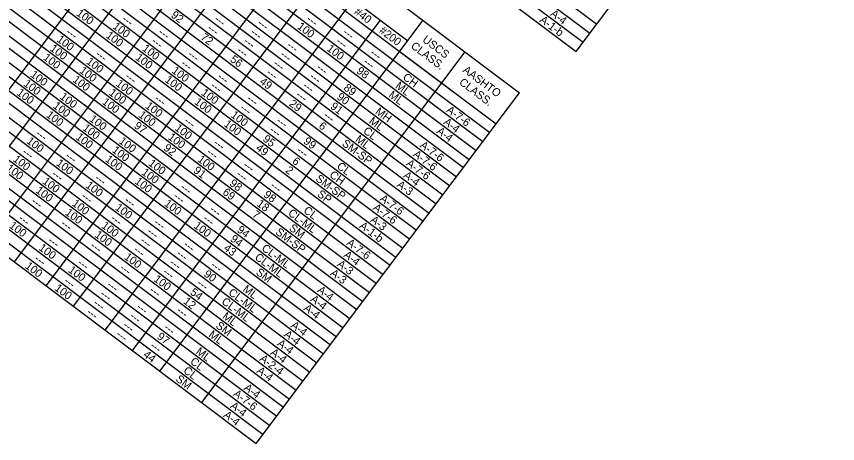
# Model space of a CAD drawing. Extents: x 627484.2 to 627514.4, y 367972.1 to 367996.9.
# Drawn here: x 627508.72 to 627514.36, y 367977.2 to 367980.14 of the extents above; entities that cross this region are included whole.
import ezdxf

# ---------------------------------------------------------------- set-up
doc = ezdxf.new("R2010")
doc.units = 0
doc.layers.add('Default', color=7, linetype='Continuous')

msp = doc.modelspace()

# ---------------------------------------------------------------- linework, layer by layer
at = {"layer": 'Default'}
for p, q in [((627508.2282, 367983.4455), (627512.7035, 367980.085)), ((627508.1814, 367983.3831), (627512.6566, 367980.0226)), ((627508.1346, 367983.3207), (627512.6098, 367979.9602)), ((627508.0877, 367983.2583), (627512.563, 367979.8978)), ((627507.6986, 367982.9746), (627512.1738, 367979.6141)), ((627507.5376, 367982.7602), (627512.0128, 367979.3997)), ((627507.4937, 367982.7017), (627511.9689, 367979.3412)), ((627507.4468, 367982.6393), (627511.9221, 367979.2788)), ((627507.4, 367982.5769), (627511.8753, 367979.2164)), ((627507.3532, 367982.5146), (627511.8284, 367979.1541)), ((627507.3122, 367982.46), (627511.7874, 367979.0995)), ((627507.2654, 367982.3976), (627511.7406, 367979.0371)), ((627507.2185, 367982.3352), (627511.6938, 367978.9747)), ((627507.1717, 367982.2729), (627511.6469, 367978.9124)), ((627512.563, 367979.8978), (627514.3574, 367982.2875)), ((627507.1248, 367982.2105), (627511.6001, 367978.85)), ((627507.078, 367982.1481), (627511.5533, 367978.7876)), ((627507.037, 367982.0936), (627511.5123, 367978.733)), ((627506.9902, 367982.0312), (627511.4654, 367978.6707)), ((627506.9434, 367981.9688), (627511.4186, 367978.6083)), ((627506.8965, 367981.9064), (627511.3718, 367978.5459)), ((627506.8497, 367981.8441), (627511.3249, 367978.4836)), ((627506.8087, 367981.7895), (627511.2839, 367978.429)), ((627506.7619, 367981.7271), (627511.2371, 367978.3666)), ((627506.715, 367981.6647), (627511.1903, 367978.3042)), ((627506.6682, 367981.6024), (627511.1434, 367978.2419)), ((627506.6214, 367981.54), (627511.0966, 367978.1795)), ((627506.5804, 367981.4854), (627511.0556, 367978.1249)), ((627506.5335, 367981.423), (627511.0088, 367978.0625)), ((627506.4867, 367981.3607), (627510.9619, 367978.0002)), ((627506.4399, 367981.2983), (627510.9151, 367977.9378)), ((627508.1116, 367978.8969), (627509.9206, 367981.306)), ((627506.3989, 367981.2437), (627510.8741, 367977.8832)), ((627506.352, 367981.1813), (627510.8273, 367977.8208)), ((627506.3052, 367981.119), (627510.7805, 367977.7585)), ((627509.8152, 367981.1657), (627511.4057, 367979.9714)), ((627506.2584, 367981.0566), (627510.7336, 367977.6961)), ((627508.2987, 367978.7564), (627510.0024, 367981.0252)), ((627506.2115, 367980.9942), (627510.6868, 367977.6337)), ((627506.1647, 367980.9319), (627510.6399, 367977.5714)), ((627506.1179, 367980.8695), (627510.5931, 367977.509)), ((627508.517, 367978.5924), (627510.2207, 367980.8613)), ((627506.0769, 367980.8149), (627510.5521, 367977.4544)), ((627506.03, 367980.7525), (627510.5053, 367977.392)), ((627508.7041, 367978.4519), (627510.4078, 367980.7207)), ((627505.9832, 367980.6902), (627510.4585, 367977.3297)), ((627505.9364, 367980.6278), (627510.4116, 367977.2673)), ((627505.8895, 367980.5654), (627510.3648, 367977.2049)), ((627508.9224, 367978.288), (627510.6261, 367980.5568)), ((627509.1095, 367978.1475), (627510.8132, 367980.4163)), ((627509.3278, 367977.9836), (627511.0315, 367980.2524)), ((627509.515, 367977.8431), (627511.2186, 367980.1119)), ((627509.7021, 367977.7026), (627511.5111, 367980.1117)), ((627509.9905, 367977.4859), (627511.7996, 367979.8951)), ((627511.3501, 367979.8973), (627512.0128, 367979.3997)), ((627510.3648, 367977.2049), (627512.1738, 367979.6141))]:
    msp.add_line(p, q, dxfattribs=at)

# ---------------------------------------------------------------- texts
for s, p in [('100', (627509.1246, 367980.1502)), ('92', (627509.7748, 367980.1375)), ('#40', (627511.0331, 367980.1589)), ('A-4', (627512.3802, 367980.147)), ('---', (627509.4374, 367980.1104)), ('---', (627510.0711, 367980.11)), ('---', (627510.3675, 367980.0826)), ('---', (627510.7049, 367980.1097)), ('A-1-b', (627512.3063, 367980.1049)), ('---', (627509.0532, 367980.0209)), ('100', (627509.3741, 367980.0603)), ('---', (627509.6869, 367980.0206)), ('---', (627510.0243, 367980.0477)), ('100', (627510.6416, 367980.0596)), ('#200', (627511.204, 367980.0306)), ('100', (627508.9899, 367979.9709)), ('100', (627509.3273, 367979.998)), ('72', (627509.9775, 367979.9853)), ('---', (627510.3207, 367980.0202)), ('---', (627510.9544, 367980.0198)), ('USCS', (627511.5013, 367979.9686)), ('100', (627508.9431, 367979.9085)), ('100', (627509.5769, 367979.9081)), ('---', (627509.6401, 367979.9582)), ('---', (627510.2738, 367979.9578)), ('---', (627510.5702, 367979.9303)), ('100', (627510.8444, 367979.9074)), ('---', (627510.9076, 367979.9574)), ('CLASS.', (627511.422, 367979.925)), ('100', (627508.8963, 367979.8461)), ('---', (627509.2559, 367979.8687)), ('100', (627509.53, 367979.8458)), ('---', (627509.8896, 367979.8683)), ('56', (627510.1801, 367979.8331)), ('---', (627510.227, 367979.8954)), ('---', (627510.5234, 367979.868)), ('---', (627511.1415, 367979.8793)), ('100', (627509.1927, 367979.8186)), ('---', (627509.8428, 367979.806)), ('---', (627510.4766, 367979.8056)), ('---', (627511.0947, 367979.8169)), ('100', (627508.8084, 367979.7292)), ('100', (627509.1458, 367979.7563)), ('100', (627509.7796, 367979.7559)), ('---', (627510.4297, 367979.7432)), ('---', (627510.7729, 367979.7781)), ('98', (627511.0484, 367979.7542)), ('AASHTO', (627511.7783, 367979.7606)), ('100', (627509.099, 367979.6939)), ('---', (627509.4586, 367979.7165)), ('100', (627509.7327, 367979.6935)), ('---', (627510.0924, 367979.7161)), ('49', (627510.383, 367979.6808)), ('---', (627510.7261, 367979.7157)), ('CH', (627511.3661, 367979.7107)), ('CLASS.', (627511.7534, 367979.6762)), ('100', (627508.7616, 367979.6668)), ('100', (627509.3954, 367979.6664)), ('---', (627510.0455, 367979.6537)), ('---', (627510.6793, 367979.6534)), ('89', (627510.9601, 367979.6376)), ('ML', (627511.3157, 367979.651)), ('100', (627508.7148, 367979.6044)), ('100', (627509.0112, 367979.577)), ('100', (627509.3485, 367979.6041)), ('100', (627509.9823, 367979.6037)), ('---', (627510.6324, 367979.591)), ('90', (627510.9131, 367979.5754)), ('ML', (627511.2688, 367979.5886)), ('100', (627508.9643, 367979.5146)), ('100', (627509.3017, 367979.5417)), ('100', (627509.5981, 367979.5142)), ('---', (627509.6613, 367979.5643)), ('100', (627509.9354, 367979.5413)), ('---', (627510.2951, 367979.5639)), ('29', (627510.5857, 367979.5286)), ('91', (627510.8691, 367979.5109)), ('100', (627508.9175, 367979.4522)), ('100', (627509.5512, 367979.4518)), ('100', (627510.185, 367979.4515)), ('---', (627510.2482, 367979.5015)), ('MH', (627511.1774, 367979.4744)), ('A-7-6', (627511.6655, 367979.4858)), ('100', (627509.2139, 367979.4247)), ('---', (627509.864, 367979.412)), ('100', (627510.1382, 367979.3891)), ('---', (627510.4978, 367979.4117)), ('---', (627510.8195, 367979.4505)), ('ML', (627511.1342, 367979.4093)), ('A-4', (627511.6457, 367979.4032)), ('100', (627509.167, 367979.3624)), ('97', (627509.5209, 367979.377)), ('100', (627509.8008, 367979.362)), ('---', (627510.4509, 367979.3493)), ('6', (627510.7889, 367979.376)), ('CL', (627511.0946, 367979.3415)), ('A-4', (627511.5988, 367979.3409)), ('100', (627508.7828, 367979.2729)), ('---', (627508.8461, 367979.3229)), ('100', (627509.1202, 367979.3)), ('100', (627509.4166, 367979.2725)), ('100', (627509.7539, 367979.2996)), ('95', (627510.4049, 367979.2863)), ('99', (627510.685, 367979.2711)), ('ML', (627511.0405, 367979.2846)), ('92', (627509.7236, 367979.2249)), ('---', (627510.0667, 367979.2598)), ('49', (627510.3573, 367979.2245)), ('SM-SP', (627510.949, 367979.2558)), ('A-7-6', (627511.4841, 367979.2441)), ('---', (627508.7524, 367979.1982)), ('100', (627509.3697, 367979.2101)), ('---', (627510.0199, 367979.1975)), ('---', (627510.6381, 367979.2088)), ('A-7-6', (627511.4372, 367979.1818)), ('100', (627508.6892, 367979.1481)), ('100', (627508.9855, 367979.1207)), ('---', (627509.0488, 367979.1707)), ('100', (627509.3229, 367979.1478)), ('100', (627509.6193, 367979.1203)), ('100', (627509.9567, 367979.1474)), ('6', (627510.6074, 367979.1343)), ('A-7-6', (627511.3904, 367979.1194)), ('100', (627508.6423, 367979.0858)), ('100', (627509.5725, 367979.0579)), ('91', (627509.9289, 367979.0707)), ('---', (627510.2695, 367979.1076)), ('2', (627510.5607, 367979.0718)), ('CL', (627510.9131, 367979.0998)), ('100', (627508.8919, 367978.9959)), ('---', (627508.9551, 367979.046)), ('---', (627509.2515, 367979.0185)), ('100', (627509.5256, 367978.9956)), ('---', (627510.2226, 367979.0452)), ('SM-SP', (627510.7675, 367979.0141)), ('CH', (627510.8626, 367979.0402)), ('A-4', (627511.3705, 367979.0368)), ('100', (627509.1883, 367978.9685)), ('---', (627509.8384, 367978.9558)), ('98', (627510.1763, 367978.9825)), ('---', (627510.4566, 367978.9671)), ('A-3', (627511.3252, 367978.9732)), ('100', (627508.845, 367978.9336)), ('---', (627509.1578, 367978.8938)), ('---', (627509.7916, 367978.8934)), ('69', (627510.129, 367978.9204)), ('98', (627510.4103, 367978.9043)), ('SP', (627510.7784, 367978.9083)), ('---', (627508.8146, 367978.8589)), ('100', (627509.0946, 367978.8437)), ('---', (627509.4542, 367978.8663)), ('100', (627509.7283, 367978.8433)), ('18', (627510.3634, 367978.842)), ('A-7-6', (627511.2089, 367978.8777)), ('100', (627509.0477, 367978.7813)), ('100', (627509.391, 367978.8162)), ('---', (627510.0411, 367978.8035)), ('7', (627510.3324, 367978.7677)), ('CL-ML', (627510.5784, 367978.7781)), ('CL', (627510.6847, 367978.7958)), ('A-7-6', (627511.1621, 367978.8153)), ('---', (627508.7268, 367978.7419)), ('---', (627509.3605, 367978.7415)), ('---', (627509.9943, 367978.7412)), ('A-3', (627511.1437, 367978.7315)), ('100', (627508.6635, 367978.6919)), ('---', (627509.0173, 367978.7066)), ('100', (627509.2973, 367978.6915)), ('---', (627509.6569, 367978.7141)), ('100', (627509.931, 367978.6911)), ('94', (627510.228, 367978.6632)), ('SM', (627510.5856, 367978.6751)), ('A-1-b', (627511.0683, 367978.6906)), ('100', (627509.2505, 367978.6291)), ('---', (627509.6101, 367978.6517)), ('94', (627510.1812, 367978.6008)), ('SM-SP', (627510.4923, 367978.6476)), ('100', (627508.8663, 367978.5396)), ('---', (627508.9295, 367978.5897)), ('---', (627509.22, 367978.5544)), ('---', (627509.5632, 367978.5893)), ('---', (627509.8596, 367978.5619)), ('A-7-6', (627510.9806, 367978.5736)), ('---', (627509.5164, 367978.527)), ('---', (627509.8128, 367978.4995)), ('43', (627510.136, 367978.5373)), ('CL-ML', (627510.3969, 367978.5364)), ('A-4', (627510.9607, 367978.491)), ('---', (627508.8358, 367978.4649)), ('100', (627509.4532, 367978.4769)), ('CL-ML', (627510.3501, 367978.474)), ('A-3', (627510.9154, 367978.4275)), ('100', (627508.7726, 367978.4149)), ('100', (627509.069, 367978.3874)), ('---', (627509.1322, 367978.4375)), ('---', (627509.4227, 367978.4022)), ('---', (627509.766, 367978.4371)), ('---', (627510.0468, 367978.4213)), ('SM', (627510.3573, 367978.371)), ('100', (627509.6559, 367978.3247)), ('---', (627509.7191, 367978.3747)), ('90', (627509.9998, 367978.3591)), ('A-3', (627510.8686, 367978.3651)), ('100', (627508.9753, 367978.2627)), ('---', (627509.0385, 367978.3127)), ('---', (627509.3349, 367978.2853)), ('---', (627509.9531, 367978.2966)), ('ML', (627510.2677, 367978.2554)), ('---', (627509.2881, 367978.2229)), ('---', (627509.6255, 367978.25)), ('54', (627509.906, 367978.2344)), ('CL-ML', (627510.1686, 367978.2323)), ('A-4', (627510.7792, 367978.2493)), ('---', (627509.2412, 367978.1605)), ('12', (627509.8594, 367978.1718)), ('CL-ML', (627510.1217, 367978.17)), ('A-4', (627510.7323, 367978.187)), ('---', (627509.5376, 367978.133)), ('---', (627509.8126, 367978.1095)), ('A-4', (627510.6855, 367978.1246)), ('---', (627509.1944, 367978.0981)), ('---', (627509.4908, 367978.0707)), ('ML', (627510.1272, 367978.0683)), ('---', (627509.444, 367978.0083)), ('---', (627509.7248, 367977.9925)), ('SM', (627510.0821, 367978.0046)), ('A-4', (627510.5977, 367978.0076)), ('---', (627509.3971, 367977.9459)), ('97', (627509.6781, 367977.9301)), ('ML', (627510.0335, 367977.9436)), ('A-4', (627510.5509, 367977.9453)), ('A-4', (627510.504, 367977.8829)), ('---', (627509.6311, 367977.8678)), ('ML', (627509.9457, 367977.8266)), ('A-4', (627510.4572, 367977.8205)), ('44', (627509.584, 367977.8056)), ('CL', (627509.9061, 367977.7588)), ('A-2-4', (627510.3833, 367977.7785)), ('CL', (627509.8593, 367977.6964)), ('A-4', (627510.3635, 367977.6958)), ('SM', (627509.807, 367977.6382)), ('A-7-6', (627510.2019, 367977.5367)), ('A-4', (627510.2757, 367977.5788)), ('A-4', (627510.182, 367977.4541)), ('A-4', (627510.1352, 367977.3917))]:
    msp.add_text(s, height=0.055, rotation=323.0968, dxfattribs=at).set_placement(p)

doc.saveas('drawing.dxf')
